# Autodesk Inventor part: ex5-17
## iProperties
Created: 2006-03
Part Number: ex5-17
Document SubType Name: Modeling
Designer: Elise Moss
Author: Elise Moss
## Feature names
1. Loft1
2. Shell1
3. Extrusion1
4. Sweep1
5. FaceDraft1
6. Fillet1
7. Fillet2
